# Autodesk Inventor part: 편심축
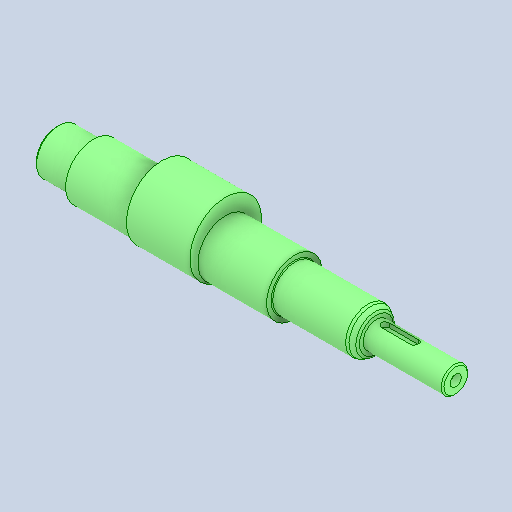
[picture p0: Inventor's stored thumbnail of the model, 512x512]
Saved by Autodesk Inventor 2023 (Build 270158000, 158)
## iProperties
Created: 2024-09
Part Number: 편심축
Material: 강철, 탄소
Document SubType Name: Modeling
Designer: home
Density: 7.85 g/cm^3
Appearance: 기본값
Author: jhkim
Sending System: Autodesk Inventor 2025
Preprocessor: ST-DEVELOPER v20
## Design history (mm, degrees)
node "편심축1"
node "솔리드2"
node "솔리드1"
